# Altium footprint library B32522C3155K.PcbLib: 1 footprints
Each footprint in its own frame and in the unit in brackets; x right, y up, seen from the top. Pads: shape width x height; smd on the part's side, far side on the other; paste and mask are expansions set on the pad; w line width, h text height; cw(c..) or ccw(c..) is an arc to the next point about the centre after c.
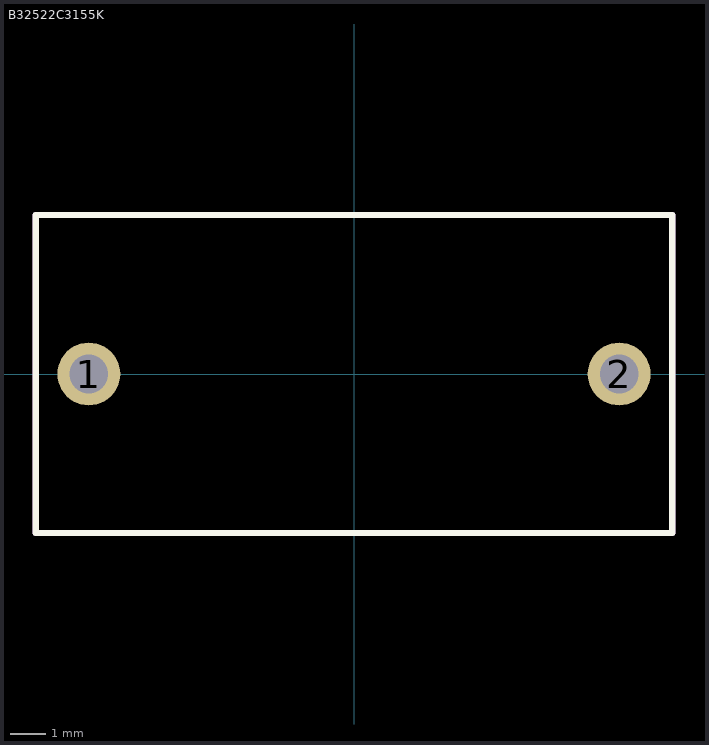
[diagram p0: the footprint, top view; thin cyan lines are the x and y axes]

## B32522C3155K [mil] "Cap EPCOS P/N B32522C3155K"
height 688.98
pads (2):
  round 70 hole 43: 1(-295.28,0) 2(295.28,0)
Top Overlay:
  lines w7: -354.33,-177.17 354.33,-177.17 354.33,177.17 -354.33,177.17 -354.33,-177.17
M5 Assembly Top:
  lines w7: -354.33,-177.17 -354.33,177.17 354.33,177.17 354.33,-177.17 -354.33,-177.17
  text ".Designator" at -173.23,-19.68 h72.83
3D body: height 688.98, standoff 0, extent -354.33,-177.17 354.33,177.17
